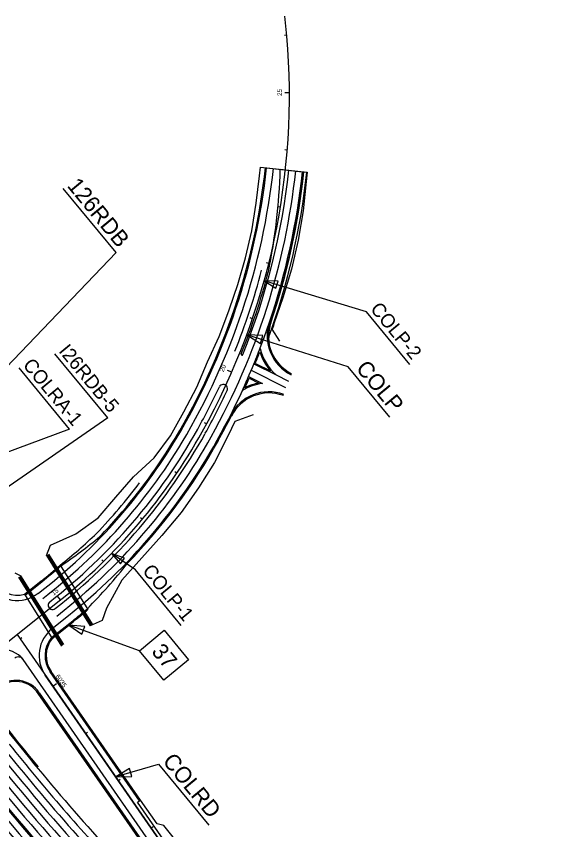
# Model space of a CAD drawing. Extents: x 1944333 to 1975203, y 788957 to 827579.
# Drawn here: x 1971381 to 1972322, y 795717 to 797131 of the extents above; entities that cross this region are included whole.
import ezdxf

# ---------------------------------------------------------------- set-up
doc = ezdxf.new("R2010")
doc.units = 0
for name, color, linetype in [('BR_CONCRETE', 7, 'Continuous'), ('RD_HC_CL_Rel', 7, 'Continuous'), ('RD_HC_Data_Tic_Rel', 7, 'Continuous'), ('RD_HC_TX_Rel_Sta50', 7, 'Continuous'), ('RD_PD_ALT1_LnLine', 7, 'Continuous'), ('RD_PD_ALT1_TrvlWay', 7, 'Continuous'), ('RD_PD_ConcMed', 7, 'Continuous'), ('RD_PD_CstnLmt', 7, 'Continuous'), ('RD_PD_FOC', 7, 'Continuous'), ('RD_PD_GR', 7, 'Continuous'), ('RD_PD_MedBWall', 7, 'Continuous'), ('RD_PD_PaveShd', 7, 'Continuous'), ('RD_PD_SW', 7, 'Continuous'), ('RD_PD_WallFill', 7, 'Continuous'), ('RD_TX_RoadID', 7, 'Continuous')]:
    doc.layers.add(name, color=color, linetype=linetype)

msp = doc.modelspace()

# ---------------------------------------------------------------- linework, layer by layer
at = {"layer": 'BR_CONCRETE'}
for p, q in [((1971457.1, 796176.9), (1971505.1, 796099.8)), ((1971395.1, 796126.3), (1971424.1, 796149.4)), ((1971395.9, 796124.9), (1971425.1, 796148.1)), ((1971395.1, 796126.3), (1971442.9, 796049.6)), ((1971442, 796051), (1971478.9, 796080.4)), ((1971442.9, 796049.6), (1971480, 796079.1))]:
    msp.add_line(p, q, dxfattribs=at)
for radius, end in [(953.5, 311.0986), (955.1, 311.0829), (1041.6, 310.3192), (1043.3, 310.3061)]:
    msp.add_arc((1970830.3, 796895.4), radius, 308.5157, end, dxfattribs=at)
at = {"layer": 'RD_HC_CL_Rel'}
for p, q in [((1971850.9, 797096.5), (1971847.9, 797131.3)), ((1971066.3, 795805.3), (1971453, 796113.1)), ((1971382, 796056.4), (1971679.3, 795627.9))]:
    msp.add_line(p, q, dxfattribs=at)
for centre, radius, start, end in [((1970655.5, 796992.7), 1200.1, 330.8981, 4.9647), ((1970830.3, 796895.4), 1000.1, 308.5157, 330.8981), ((1974296, 798203.9), 3819.7, 216.3977, 243.9112), ((1972851.5, 796739.9), 1996, 210.7638, 246.9227)]:
    msp.add_arc(centre, radius, start, end, dxfattribs=at)
at = {"layer": 'RD_HC_Data_Tic_Rel'}
for p, q in [((1971850.9, 797098.3), (1971846.9, 797097.9)), ((1971855.5, 796998.4), (1971847.5, 796998.4)), ((1971851.8, 796898.5), (1971847.8, 796898.8)), ((1971839.8, 796799.2), (1971835.9, 796799.9)), ((1971819.6, 796701.3), (1971815.8, 796702.3)), ((1971791.3, 796605.4), (1971787.6, 796606.7)), ((1971755.2, 796512.2), (1971747.8, 796515.5)), ((1971711.4, 796422.4), (1971707.8, 796424.3)), ((1971659.7, 796336.8), (1971656.4, 796339)), ((1971599.8, 796256.8), (1971596.7, 796259.3)), ((1971532.2, 796183.2), (1971529.4, 796186)), ((1971457.6, 796116.6), (1971452.6, 796122.9)), ((1971387.2, 796048.8), (1971390.5, 796051.1)), ((1971444.2, 795966.7), (1971450.8, 795971.3)), ((1971501.3, 795884.5), (1971504.5, 795886.8)), ((1971558.3, 795802.4), (1971561.6, 795804.7)), ((1971615.3, 795720.2), (1971618.6, 795722.5))]:
    msp.add_line(p, q, dxfattribs=at)
at = {"layer": 'RD_PD_ALT1_LnLine'}
for p, q in [((1971832.5, 796507.6), (1971832.5, 796507.6)), ((1971832.5, 796507.6), (1971854.3, 796496.7)), ((1971451.1, 796088.5), (1971464.2, 796098.9))]:
    msp.add_line(p, q, dxfattribs=at)
for centre, radius, start, end in [((1970655.5, 796992.7), 1179, 329.2865, 353.8529), ((1970655.5, 796992.7), 1218, 330.8981, 353.8529), ((1970655.5, 796992.7), 1191, 338.1146, 345.2587), ((1970830.3, 796895.4), 1018, 308.5157, 330.8981), ((1970830.3, 796895.4), 979, 307.536, 328.9573), ((1971357.3, 795985), 45, 38.2884, 97.4352), ((1974296, 798203.9), 3758.7, 217.2297, 223.1115), ((1974296, 798203.9), 3782.7, 217.2379, 225.5447), ((1974296, 798203.9), 3770.7, 217.2585, 225.5447), ((1974296, 798203.9), 3794.7, 217.2419, 225.5447), ((1974296, 798203.9), 3844.7, 217.2585, 243.9112), ((1974296, 798203.9), 3868.7, 217.2663, 243.9112), ((1974296, 798203.9), 3856.7, 217.2624, 243.9112)]:
    msp.add_arc(centre, radius, start, end, dxfattribs=at)
at = {"layer": 'RD_PD_ALT1_TrvlWay'}
for p, q in [((1971815.8, 796867.7), (1971878.5, 796861)), ((1971793.9, 796526.8), (1971832.5, 796507.6)), ((1971789.3, 796515.7), (1971849, 796486)), ((1971784.6, 796504.7), (1971808.8, 796492.6)), ((1971443.1, 796066.7), (1971471.7, 796089.5)), ((1971666.2, 795618.8), (1971392.7, 796013)), ((1971679.3, 795627.9), (1971431.1, 795985.6))]:
    msp.add_line(p, q, dxfattribs=at)
for centre, radius, start, end in [((1970655.5, 796992.7), 1167, 329.2694, 353.8529), ((1970655.5, 796992.7), 1206, 338.1146, 353.8529), ((1970797.8, 796895.7), 1042.4, 348.4252, 358.3194), ((1970655.5, 796992.7), 1230, 341.3416, 353.8529), ((1970655.5, 796992.7), 1203, 338.1146, 345.2587), ((1970655.5, 796992.7), 1230, 330.8981, 341.3416), ((1971892, 796575.2), 75, 161.3416, 243.5021), ((1970655.5, 796992.7), 1230, 337.7449, 339.0916), ((1971892, 796575.2), 90, 193.7906, 228.667), ((1971773.2, 796543.7), 1.5, 158.1146, 338.1146), ((1970655.5, 796992.7), 1230, 335.4009, 336.6247), ((1970655.5, 796992.7), 1191, 330.8981, 334.8705), ((1970655.5, 796992.7), 1206, 330.8981, 334.8705), ((1971740.6, 796483.7), 7.5, 334.8705, 154.8705), ((1971819.9, 796403.3), 90, 97.0594, 120.7019), ((1971819.9, 796403.3), 75, 69.76, 153.1509), ((1970830.3, 796895.4), 991, 307.8944, 330.8981), ((1970830.3, 796895.4), 1006, 307.8944, 330.8981), ((1970830.3, 796895.4), 1030, 308.5157, 330.8981), ((1970830.3, 796895.4), 967, 318.9315, 328.9325), ((1970830.3, 796895.4), 967, 307.4711, 318.9315), ((1971382.1, 796175.6), 60, 214.7587, 307.4711), ((1971443.6, 796107.5), 7.5, 127.8944, 307.8944), ((1971480.4, 796019.8), 60, 128.5157, 214.7587), ((1971384.4, 796007.3), 10, 34.7587, 128.5157), ((1974296, 798203.9), 3806.7, 217.2459, 225.5447), ((1974296, 798203.9), 3832.7, 217.2545, 243.9112), ((1974296, 798203.9), 3746.7, 218.6115, 223.1115), ((1974296, 798203.9), 3880.7, 217.2701, 243.9112), ((1972851.5, 796739.9), 1984, 210.7638, 234.3208)]:
    msp.add_arc(centre, radius, start, end, dxfattribs=at)
at = {"layer": 'RD_PD_ConcMed'}
for centre, radius, start, end in [((1970655.5, 796992.7), 1191, 330.8981, 334.8705), ((1970655.5, 796992.7), 1206, 330.8981, 334.8705), ((1971740.6, 796483.7), 7.5, 334.8705, 154.8705), ((1970830.3, 796895.4), 991, 307.8944, 330.8981), ((1970830.3, 796895.4), 1006, 307.8944, 330.8981), ((1971443.6, 796107.5), 7.5, 127.8944, 307.8944)]:
    msp.add_arc(centre, radius, start, end, dxfattribs=at)
at = {"layer": 'RD_PD_CstnLmt'}
for p, q in [((1971838.7, 796566.5), (1971825.7, 796587.2)), ((1971792.4, 796438.5), (1971760.7, 796426.5)), ((1971433.1, 796193.5), (1971509.1, 796071.7)), ((1971378.2, 796163.3), (1971388.6, 796158.4)), ((1971463.2, 796038.7), (1971388.6, 796158.4))]:
    msp.add_line(p, q, dxfattribs=at)
for points in [[(1971433.1, 796193.5), (1971439.9, 796211.6), (1971484.4, 796231.6), (1971523, 796259.5), (1971553.6, 796295.1), (1971584.7, 796330.6), (1971620.3, 796363.4), (1971648.6, 796401.9), (1971672.2, 796443.5), (1971694.5, 796486.2), (1971713.2, 796530.6), (1971733.2, 796574.4), (1971750.4, 796619.4), (1971751.4, 796622.6), (1971766.1, 796665), (1971779.3, 796711.4), (1971790.3, 796758.4), (1971797.6, 796806.1), (1971803.5, 796854), (1971805.1, 796868.9), (1971886.7, 796860.1), (1971885, 796844.1), (1971879.3, 796792.8), (1971871, 796741.8), (1971859.2, 796691.4), (1971844.3, 796641.9), (1971828.7, 796596.5), (1971827.7, 796593.1), (1971825.7, 796587.2)], [(1971760.7, 796426.5), (1971748.9, 796402.1), (1971725.1, 796355.7), (1971697.8, 796311.1), (1971667.4, 796268.6), (1971633.9, 796228.5), (1971598.8, 796189.9), (1971564.2, 796150.7), (1971537.6, 796101.9), (1971530.1, 796080.9), (1971509.1, 796071.7)], [(1971663, 795692.5), (1971637.4, 795724.2), (1971625.6, 795727.4), (1971596.6, 795768.1)]]:
    msp.add_lwpolyline(points, dxfattribs=at)
at = {"layer": 'RD_PD_FOC'}
for centre, radius, start, end in [((1970655.5, 796992.7), 1165, 329.2694, 353.8529), ((1970655.5, 796992.7), 1232, 341.3416, 353.8529), ((1971892, 796575.2), 73, 161.3416, 243.5021), ((1971819.9, 796403.3), 73, 69.76, 153.1509), ((1970655.5, 796992.7), 1232, 330.8981, 333.1509), ((1970830.3, 796895.4), 965, 318.9315, 328.9325), ((1970830.3, 796895.4), 1032, 316.128, 330.8981), ((1970830.3, 796895.4), 965, 316.128, 318.9315), ((1970922.2, 796958.6), 948.9, 304.3774, 309.5167), ((1970750.4, 796839.8), 1055.4, 315.5858, 321.316)]:
    msp.add_arc(centre, radius, start, end, dxfattribs=at)
at = {"layer": 'RD_PD_GR'}
for centre, radius, start, end in [((1970830.3, 796895.4), 957, 316.128, 323.039), ((1970863.4, 796918.1), 949.7, 308.6931, 313.7563), ((1971382.9, 796175.3), 50.5, 213.8568, 283.996), ((1974296, 798203.9), 3732.7, 217.2515, 219.5714)]:
    msp.add_arc(centre, radius, start, end, dxfattribs=at)
at = {"layer": 'RD_PD_MedBWall'}
for radius, start in [(3820.7, 217.2581), (3818.7, 217.2574)]:
    msp.add_arc((1974296, 798203.9), radius, start, 243.9112, dxfattribs=at)
at = {"layer": 'RD_PD_PaveShd'}
for p, q in [((1971796.5, 796527.8), (1971822.5, 796514.8)), ((1971785.6, 796501.9), (1971802.3, 796493.6)), ((1971591.7, 795764.7), (1971595, 795767)), ((1971684.2, 795631.4), (1971591.7, 795764.7))]:
    msp.add_line(p, q, dxfattribs=at)
for centre, radius, start, end in [((1970655.5, 796992.7), 1232, 337.8313, 338.8113), ((1971892, 796575.2), 92, 197.5829, 221.0071), ((1970655.5, 796992.7), 1232, 335.6811, 336.5264), ((1971819.9, 796403.3), 92, 100.9904, 116.9096), ((1971382.6, 796174.6), 49.9, 213.4478, 284.4588), ((1974296, 798203.9), 3734.7, 217.2214, 223.1156), ((1974296, 798203.9), 3892.7, 217.274, 242.8933), ((1972851.5, 796739.9), 1980, 210.7638, 228.8892)]:
    msp.add_arc(centre, radius, start, end, dxfattribs=at)
at = {"layer": 'RD_PD_SW'}
msp.add_line((1971839.7, 796865.2), (1971854.6, 796863.5), dxfattribs=at)
for centre, radius, start, end in [((1970655.5, 796992.7), 1237.5, 340.1487, 353.8529), ((1970655.5, 796992.7), 1232.5, 341.3416, 353.8529), ((1971892, 796575.2), 72.5, 161.3416, 182.1564)]:
    msp.add_arc(centre, radius, start, end, dxfattribs=at)
at = {"layer": 'RD_PD_WallFill'}
for p, q in [((1971434, 796194.1), (1971510, 796072.3)), ((1971435.7, 796195.1), (1971511.7, 796073.3)), ((1971436.9, 796195.9), (1971512.9, 796074.1)), ((1971384.8, 796156), (1971459.4, 796036.3)), ((1971386.1, 796156.8), (1971460.7, 796037.1)), ((1971595, 795767), (1971439.4, 795991.3)), ((1971596.6, 795768.1), (1971441.3, 795992)), ((1971656.3, 795612), (1971419, 795954)), ((1971420.6, 795955.2), (1971658, 795613.1)), ((1971596.6, 795768.1), (1971595, 795767))]:
    msp.add_line(p, q, dxfattribs=at)
msp.add_lwpolyline([(1971462.4, 796038.2), (1971387.8, 796157.8)], dxfattribs=at)
for centre, radius, start, end in [((1971480.3, 796019.4), 49.7, 140.4273, 214.488), ((1971480.3, 796019.4), 47.7, 141.2325, 215.035), ((1971379.5, 795926.7), 50, 34.7587, 128.5152), ((1971379.5, 795926.7), 48, 34.7587, 128.5152)]:
    msp.add_arc(centre, radius, start, end, dxfattribs=at)
at = {"layer": 'RD_TX_RoadID'}
for p, q in [((1971554.2, 796720.6), (1971462.5, 796831.6)), ((1972065.1, 796526), (1971989.6, 796617.4)), ((1971539.8, 796433), (1971447.9, 796544.2)), ((1972030.3, 796434.4), (1971957.9, 796522)), ((1971473.3, 796413.4), (1971385.5, 796519.9)), ((1971667.5, 796072.2), (1971587.7, 796168.8)), ((1971716.1, 795724.9), (1971628.4, 795831.1))]:
    msp.add_line(p, q, dxfattribs=at)
for points in [[(1971554.2, 796720.6), (1971120, 796267.5)], [(1971989.6, 796617.4), (1971811.8, 796671.5)], [(1971957.9, 796522), (1971781.4, 796577.5)], [(1971539.8, 796433), (1971166.3, 796174.4)], [(1971473.3, 796413.4), (1971192.3, 796309.3)], [(1971587.7, 796168.8), (1971546.4, 796197.4)], [(1971594.8, 796028), (1971471.9, 796072.8)], [(1971627.5, 795830.4), (1971553.7, 795808.9)]]:
    msp.add_lwpolyline(points, dxfattribs=at)
for points in [[(1971835.8, 796670.7), (1971811.8, 796671.5), (1971832.1, 796658.8)], [(1971809.4, 796576.3), (1971781.4, 796577.5), (1971805.1, 796562.5)], [(1971569, 796189.3), (1971546.4, 796197.4), (1971561.9, 796179.1)], [(1971499.8, 796070.3), (1971471.9, 796072.8), (1971494.9, 796056.7)], [(1971638, 796063.7), (1971680.3, 796012.4), (1971637.1, 795976.8), (1971594.8, 796028)], [(1971577.7, 795823.4), (1971553.7, 795808.9), (1971581.7, 795809.5)]]:
    msp.add_lwpolyline(points, close=True, dxfattribs=at)

# ---------------------------------------------------------------- texts
at = {"layer": 'RD_HC_TX_Rel_Sta50'}
for s, rotation, p in [('25', 90.2724, (1971842.6, 796992.7)), ('20', 66.3991, (1971741, 796512.3)), ('15', 38.8515, (1971445.6, 796123.7)), ('6035', 304.7587, (1971448.4, 795983.5))]:
    msp.add_text(s, height=8, rotation=rotation, dxfattribs=at).set_placement(p)
at = {"layer": 'RD_TX_RoadID'}
for s, height, p in [('126RDB', 28, (1971467.9, 796836.1)), ('COLP-2', 24, (1971995, 796621.8)), ('I26RDB-5', 24, (1971453.3, 796548.7)), ('COLRA-1', 24, (1971390.9, 796524.3)), (' COLP', 28, (1971963.3, 796526.5)), (' COLP-1', 24, (1971593.1, 796173.3)), ('37', 28, (1971614.5, 796026.1)), ('COLRD', 28, (1971633.8, 795835.6))]:
    msp.add_text(s, height=height, rotation=309.5517, dxfattribs=at).set_placement(p)

doc.saveas('drawing.dxf')
